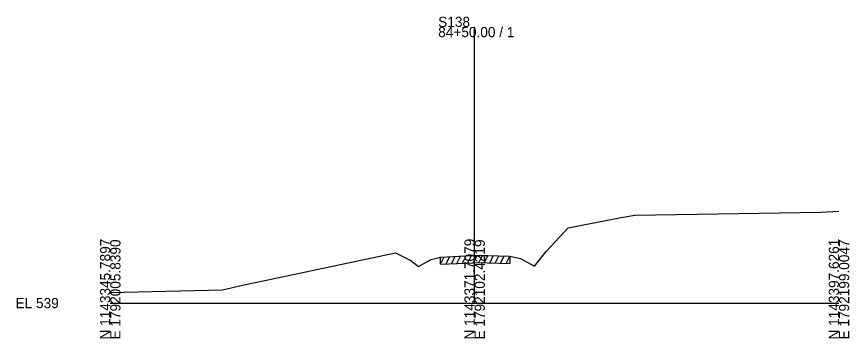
# Model space of a CAD drawing. Extents: x -26 to 1203, y -10 to 19606.
# Drawn here: x -25.7 to 202.8, y 8990.3 to 9078.7 of the extents above; entities that cross this region are included whole.
import ezdxf

# ---------------------------------------------------------------- set-up
doc = ezdxf.new("R2010")
doc.units = 0
for name, color, linetype in [('RD_EX_Driveway', 7, 'Continuous'), ('RD_GPK_XS_Cell', 7, 'Continuous'), ('RD_XS_ExGround', 7, 'Continuous'), ('RD_XS_ExPaveRet', 7, 'Continuous')]:
    doc.layers.add(name, color=color, linetype=linetype)

msp = doc.modelspace()

# ---------------------------------------------------------------- linework, layer by layer
at = {"layer": 'RD_GPK_XS_Cell'}
for p, q in [((100, 9000), (100, 9075.86)), ((0, 9000), (100, 9000)), ((100, 9000), (200, 9000))]:
    msp.add_line(p, q, dxfattribs=at)
at = {"layer": 'RD_XS_ExGround'}
msp.add_lwpolyline([(0, 9002.9), (30.82, 9003.66), (37.1, 9005.1), (44.17, 9006.59), (78.24, 9013.79), (82.51, 9011.67), (84.61, 9010.08), (87.06, 9011.39), (88, 9011.94), (88.82, 9012.16), (90.64, 9012.66), (97.49, 9013), (100, 9013.1), (100.63, 9013.12), (103.5, 9013.03), (109.65, 9012.87), (111.74, 9012.45), (112.63, 9012.28), (115.27, 9010.79), (116.42, 9010.13), (119.67, 9014.16), (125.64, 9020.71), (140.18, 9023.48), (143.93, 9024.19), (195, 9025.02), (200, 9025.29)], dxfattribs=at)
at = {"layer": 'RD_XS_ExPaveRet'}
for p, q in [((90.64, 9010.66), (91.66, 9012.71)), ((90.64, 9010.66), (90.64, 9012.66)), ((92.14, 9010.73), (93.16, 9012.78)), ((93.64, 9010.81), (94.66, 9012.86)), ((95.14, 9010.88), (96.16, 9012.93)), ((96.64, 9010.96), (97.66, 9013.01)), ((97.49, 9011), (100, 9011.1)), ((98.14, 9011.03), (99.16, 9013.07)), ((99.64, 9011.08), (100.66, 9013.12)), ((100, 9011.1), (100.63, 9011.12)), ((100.63, 9011.12), (103.5, 9011.03)), ((101.14, 9011.1), (102.12, 9013.07)), ((102.64, 9011.05), (103.62, 9013.02)), ((104.14, 9011.01), (105.13, 9012.99)), ((105.64, 9010.97), (106.63, 9012.95)), ((107.14, 9010.94), (108.13, 9012.91)), ((108.64, 9010.9), (109.63, 9012.87)), ((109.65, 9012.87), (109.65, 9010.87)), ((90.64, 9010.66), (97.49, 9011)), ((103.5, 9011.03), (109.65, 9010.87))]:
    msp.add_line(p, q, dxfattribs=at)

# ---------------------------------------------------------------- texts
at = {"layer": 'RD_EX_Driveway'}
msp.add_text('545.55', height=0.0975, rotation=90, dxfattribs=at).set_placement((100.1, 9013.1))
at = {"layer": 'RD_GPK_XS_Cell'}
for s, p in [('S138', (90, 9075.86)), ('84+50.00 / 1', (90, 9073.06)), ('EL 539', (-26, 8998.6))]:
    msp.add_text(s, height=2.8, dxfattribs=at).set_placement(p)
for s, p in [('N 1143345.7897', (0, 8990)), ('E 1792005.8390', (2.8, 8990)), ('N 1143371.7079', (100, 8990)), ('E 1792102.4219', (102.8, 8990)), ('N 1143397.6261', (200, 8990)), ('E 1792199.0047', (202.8, 8990))]:
    msp.add_text(s, height=2.8, rotation=90, dxfattribs=at).set_placement(p)

doc.saveas('drawing.dxf')
